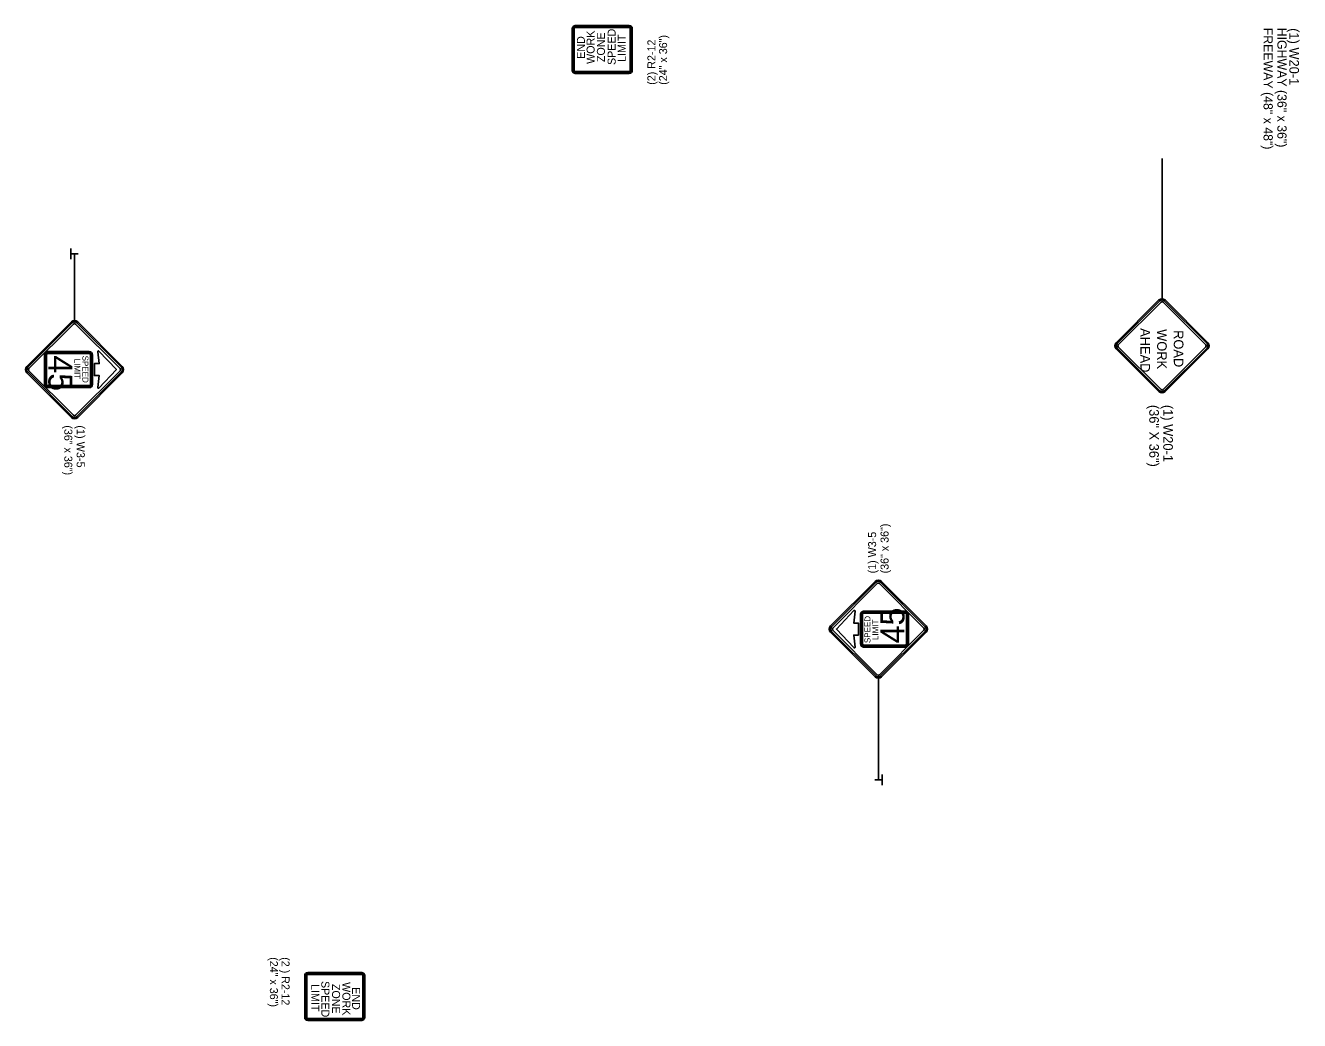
# Model space of a CAD drawing. Extents: x 1930579 to 1939784, y 596179 to 597522.
# Drawn here: x 1936300 to 1937255, y 596326 to 597073 of the extents above; entities that cross this region are included whole.
import ezdxf

# ---------------------------------------------------------------- set-up
doc = ezdxf.new("R2010")
doc.units = 0
for name, color, linetype in [('Default', 7, 'Continuous'), ('P_TC_Signs_Permanent', 7, 'Continuous'), ('P_TC_Signs_Temporary', 7, 'Continuous'), ('R_Annotation', 7, 'Continuous')]:
    doc.layers.add(name, color=color, linetype=linetype)

msp = doc.modelspace()

# ---------------------------------------------------------------- linework, layer by layer
at = {"layer": 'Default'}
for p, q in [((1936334.02, 596897.4), (1936334.02, 596905.4)), ((1936334.14, 596901.38), (1936339.61, 596901.38)), ((1936942.3, 596506.94), (1936936.84, 596506.94)), ((1936942.42, 596510.92), (1936942.42, 596502.91))]:
    msp.add_line(p, q, dxfattribs=at)
at = {"layer": 'P_TC_Signs_Permanent'}
for p, q in [((1936710.08, 597070.44), (1936710.08, 597038.94)), ((1936710.64, 597070.44), (1936710.64, 597038.94)), ((1936711.58, 597070.44), (1936711.58, 597038.94)), ((1936752.83, 597072.69), (1936712.33, 597072.69)), ((1936752.83, 597072.13), (1936712.33, 597072.13)), ((1936752.83, 597071.19), (1936712.33, 597071.19)), ((1936753.58, 597038.94), (1936753.58, 597070.44)), ((1936754.52, 597038.94), (1936754.52, 597070.44)), ((1936755.08, 597038.94), (1936755.08, 597070.44)), ((1936712.33, 597038.19), (1936752.83, 597038.19)), ((1936712.33, 597037.25), (1936752.83, 597037.25)), ((1936712.33, 597036.69), (1936752.83, 597036.69)), ((1936334.49, 596850.41), (1936301.08, 596816.99)), ((1936335.15, 596849.74), (1936301.74, 596816.33)), ((1936336.08, 596848.81), (1936302.67, 596815.4)), ((1936371.08, 596815.4), (1936337.67, 596848.81)), ((1936372.01, 596816.33), (1936338.6, 596849.74)), ((1936372.67, 596816.99), (1936339.26, 596850.41)), ((1936316.68, 596828.11), (1936347.88, 596828.11)), ((1936314.28, 596803.51), (1936314.28, 596825.71)), ((1936350.28, 596825.71), (1936350.28, 596803.51)), ((1936301.08, 596812.22), (1936334.49, 596778.81)), ((1936301.74, 596812.88), (1936335.15, 596779.47)), ((1936302.67, 596813.81), (1936336.08, 596780.4)), ((1936337.67, 596780.4), (1936371.08, 596813.81)), ((1936338.6, 596779.47), (1936372.01, 596812.88)), ((1936339.26, 596778.81), (1936372.67, 596812.22)), ((1936347.88, 596801.11), (1936316.68, 596801.11)), ((1936937.18, 596655.81), (1936903.77, 596622.4)), ((1936937.85, 596655.15), (1936904.43, 596621.74)), ((1936974.7, 596621.74), (1936941.29, 596655.15)), ((1936975.37, 596622.4), (1936941.96, 596655.81)), ((1936938.77, 596654.22), (1936905.36, 596620.81)), ((1936973.78, 596620.81), (1936940.36, 596654.22)), ((1936926.16, 596608.91), (1936926.16, 596631.11)), ((1936928.56, 596633.51), (1936959.76, 596633.51)), ((1936962.16, 596631.11), (1936962.16, 596608.91)), ((1936903.77, 596617.63), (1936937.18, 596584.22)), ((1936904.43, 596618.29), (1936937.85, 596584.88)), ((1936905.36, 596619.22), (1936938.77, 596585.81)), ((1936940.36, 596585.81), (1936973.78, 596619.22)), ((1936941.29, 596584.88), (1936974.7, 596618.29)), ((1936941.96, 596584.22), (1936975.37, 596617.63)), ((1936959.76, 596606.51), (1936928.56, 596606.51)), ((1936509.45, 596360.24), (1936509.45, 596328.74)), ((1936510.01, 596360.24), (1936510.01, 596328.74)), ((1936510.95, 596360.24), (1936510.95, 596328.74)), ((1936552.2, 596362.49), (1936511.7, 596362.49)), ((1936552.2, 596361.93), (1936511.7, 596361.93)), ((1936552.2, 596360.99), (1936511.7, 596360.99)), ((1936552.95, 596328.74), (1936552.95, 596360.24)), ((1936553.88, 596328.74), (1936553.88, 596360.24)), ((1936554.45, 596328.74), (1936554.45, 596360.24)), ((1936511.7, 596327.99), (1936552.2, 596327.99)), ((1936511.7, 596327.05), (1936552.2, 596327.05)), ((1936511.7, 596326.49), (1936552.2, 596326.49))]:
    msp.add_line(p, q, dxfattribs=at)
for points in [[(1936347.88, 596827.51), (1936316.68, 596827.51)], [(1936316.68, 596826.61), (1936347.88, 596826.61)], [(1936354.23, 596828.07), (1936355.35, 596819.11), (1936351.78, 596819.11), (1936351.78, 596810.11), (1936355.34, 596810.11), (1936354.23, 596801.22)], [(1936355.19, 596800.76), (1936368.28, 596814.64), (1936355.19, 596828.52)], [(1936314.88, 596825.71), (1936314.88, 596803.51)], [(1936315.78, 596803.51), (1936315.78, 596825.71)], [(1936348.78, 596825.71), (1936348.78, 596814.61), (1936348.78, 596803.51)], [(1936349.68, 596803.51), (1936349.68, 596814.61), (1936349.68, 596825.71)], [(1936347.88, 596802.61), (1936316.68, 596802.61)], [(1936316.68, 596801.71), (1936347.88, 596801.71)], [(1936921.25, 596633.86), (1936908.16, 596619.98), (1936921.25, 596606.1)], [(1936922.22, 596606.55), (1936921.1, 596615.51), (1936924.66, 596615.51), (1936924.66, 596624.51), (1936921.1, 596624.51), (1936922.22, 596633.4)], [(1936926.76, 596631.11), (1936926.76, 596620.01), (1936926.76, 596608.91)], [(1936927.66, 596608.91), (1936927.66, 596620.01), (1936927.66, 596631.11)], [(1936959.76, 596632.91), (1936928.56, 596632.91)], [(1936928.56, 596632.01), (1936959.76, 596632.01)], [(1936960.66, 596631.11), (1936960.66, 596608.91)], [(1936961.56, 596608.91), (1936961.56, 596631.11)], [(1936959.76, 596608.01), (1936928.56, 596608.01)], [(1936928.56, 596607.11), (1936959.76, 596607.11)]]:
    msp.add_lwpolyline(points, dxfattribs=at)
for centre, radius, start, end in [((1936712.33, 597070.44), 2.25, 90, 180), ((1936712.33, 597070.44), 1.69, 90, 180), ((1936712.33, 597070.44), 0.75, 90, 180), ((1936752.83, 597070.44), 2.25, 360, 90), ((1936752.83, 597070.44), 1.69, 360, 90), ((1936752.83, 597070.44), 0.75, 360, 90), ((1936712.33, 597038.94), 2.25, 180, 270), ((1936712.33, 597038.94), 1.69, 180, 270), ((1936712.33, 597038.94), 0.75, 180, 270), ((1936752.83, 597038.94), 2.25, 270, 360), ((1936752.83, 597038.94), 1.69, 270, 360), ((1936752.83, 597038.94), 0.75, 270, 360), ((1936336.87, 596848.02), 3.38, 45, 135), ((1936336.87, 596848.02), 2.44, 45, 135), ((1936336.87, 596848.02), 1.13, 45, 135), ((1936316.68, 596825.71), 2.4, 90, 180), ((1936316.68, 596825.71), 1.8, 90, 180), ((1936316.68, 596825.71), 0.9, 90, 180), ((1936347.88, 596825.71), 2.4, 360, 90), ((1936347.88, 596825.71), 1.8, 360, 90), ((1936347.88, 596825.71), 0.9, 360, 90), ((1936354.79, 596828.14), 0.563, 43.31166, 187.12501), ((1936303.46, 596814.61), 3.38, 135, 225), ((1936370.28, 596814.61), 3.38, 315, 45), ((1936303.46, 596814.61), 2.44, 135, 225), ((1936303.46, 596814.61), 1.13, 135, 225), ((1936370.28, 596814.61), 1.13, 315, 45), ((1936370.28, 596814.61), 2.44, 315, 45), ((1936316.68, 596803.51), 2.4, 180, 270), ((1936316.68, 596803.51), 1.8, 180, 270), ((1936316.68, 596803.51), 0.9, 180, 270), ((1936347.88, 596803.51), 2.4, 270, 360), ((1936347.88, 596803.51), 1.8, 270, 360), ((1936347.88, 596803.51), 0.9, 270, 360), ((1936354.79, 596801.15), 0.563, 172.87498, 316.68834), ((1936336.87, 596781.2), 3.38, 225, 315), ((1936336.87, 596781.2), 2.44, 225, 315), ((1936336.87, 596781.2), 1.13, 225, 315), ((1936939.57, 596653.42), 3.38, 45, 135), ((1936939.57, 596653.42), 2.44, 45, 135), ((1936939.57, 596653.42), 1.13, 45, 135), ((1936921.66, 596633.47), 0.563, 352.87498, 136.68834), ((1936928.56, 596631.11), 2.4, 90, 180), ((1936928.56, 596631.11), 1.8, 90, 180), ((1936928.56, 596631.11), 0.9, 90, 180), ((1936959.76, 596631.11), 2.4, 360, 90), ((1936959.76, 596631.11), 1.8, 360, 90), ((1936959.76, 596631.11), 0.9, 360, 90), ((1936906.16, 596620.01), 3.38, 135, 225), ((1936906.16, 596620.01), 2.44, 135, 225), ((1936906.16, 596620.01), 1.13, 135, 225), ((1936972.98, 596620.01), 1.13, 315, 45), ((1936972.98, 596620.01), 2.44, 315, 45), ((1936972.98, 596620.01), 3.38, 315, 45), ((1936921.66, 596606.48), 0.563, 223.31166, 7.12501), ((1936928.56, 596608.91), 2.4, 180, 270), ((1936928.56, 596608.91), 1.8, 180, 270), ((1936928.56, 596608.91), 0.9, 180, 270), ((1936959.76, 596608.91), 2.4, 270, 360), ((1936959.76, 596608.91), 1.8, 270, 360), ((1936959.76, 596608.91), 0.9, 270, 360), ((1936939.57, 596586.6), 3.38, 225, 315), ((1936939.57, 596586.6), 2.44, 225, 315), ((1936939.57, 596586.6), 1.13, 225, 315), ((1936511.7, 596360.24), 2.25, 90, 180), ((1936511.7, 596360.24), 1.69, 90, 180), ((1936511.7, 596360.24), 0.75, 90, 180), ((1936552.2, 596360.24), 2.25, 360, 90), ((1936552.2, 596360.24), 1.69, 360, 90), ((1936552.2, 596360.24), 0.75, 360, 90), ((1936511.7, 596328.74), 2.25, 180, 270), ((1936511.7, 596328.74), 1.69, 180, 270), ((1936511.7, 596328.74), 0.75, 180, 270), ((1936552.2, 596328.74), 2.25, 270, 360), ((1936552.2, 596328.74), 1.69, 270, 360), ((1936552.2, 596328.74), 0.75, 270, 360)]:
    msp.add_arc(centre, radius, start, end, dxfattribs=at)
at = {"layer": 'P_TC_Signs_Temporary'}
for p, q in [((1937117.92, 596834.77), (1937149.99, 596866.84)), ((1937118.55, 596834.13), (1937150.63, 596866.2)), ((1937119.44, 596833.24), (1937151.52, 596865.31)), ((1937153.04, 596865.31), (1937185.12, 596833.24)), ((1937153.94, 596866.2), (1937186.01, 596834.13)), ((1937154.57, 596866.84), (1937186.65, 596834.77)), ((1937149.99, 596798.11), (1937117.92, 596830.18)), ((1937150.63, 596798.75), (1937118.55, 596830.82)), ((1937151.52, 596799.64), (1937119.44, 596831.71)), ((1937185.12, 596831.71), (1937153.04, 596799.64)), ((1937186.01, 596830.82), (1937153.94, 596798.75)), ((1937186.65, 596830.18), (1937154.57, 596798.11))]:
    msp.add_line(p, q, dxfattribs=at)
for centre, radius, start, end in [((1937152.28, 596864.55), 3.24, 45, 135), ((1937152.28, 596864.55), 2.34, 45, 135), ((1937152.28, 596864.55), 1.08, 45, 135), ((1937120.21, 596832.47), 3.24, 135, 225), ((1937120.21, 596832.47), 2.34, 135, 225), ((1937120.21, 596832.47), 1.08, 135, 225), ((1937184.36, 596832.47), 1.08, 315, 45), ((1937184.36, 596832.47), 2.34, 315, 45), ((1937184.36, 596832.47), 3.24, 315, 45), ((1937152.28, 596800.4), 3.24, 225, 315), ((1937152.28, 596800.4), 2.34, 225, 315), ((1937152.28, 596800.4), 1.08, 225, 315)]:
    msp.add_arc(centre, radius, start, end, dxfattribs=at)
at = {"layer": 'R_Annotation'}
for p, q in [((1937152.28, 596972.99), (1937152.28, 596867.79)), ((1937152.28, 596972.99), (1937152.28, 596867.79)), ((1936336.87, 596901.38), (1936336.87, 596851.39)), ((1936939.57, 596506.94), (1936939.57, 596583.23))]:
    msp.add_line(p, q, dxfattribs=at)

# ---------------------------------------------------------------- texts
at = {"layer": 'P_TC_Signs_Permanent'}
for s, height, rotation, p in [('WORK', 6, 90, (1936726.82, 597043.89)), ('ZONE', 6, 90, (1936734.56, 597045.22)), ('SPEED', 6, 90, (1936742.58, 597043.05)), ('LIMIT', 6, 90, (1936750.21, 597045.4)), ('END', 6, 90, (1936719.53, 597047.7)), ('45', 18, 270, (1936317.28, 596825.29)), ('LIMIT', 4.5, 270, (1936336.78, 596822.8)), ('SPEED', 4.5, 270, (1936342.78, 596825.11)), ('SPEED', 4.5, 90, (1936933.66, 596609.51)), ('LIMIT', 4.5, 90, (1936939.66, 596611.82)), ('45', 18, 90, (1936959.16, 596609.33)), ('LIMIT', 6, 270, (1936514.32, 596353.78)), ('SPEED', 6, 270, (1936521.95, 596356.13)), ('ZONE', 6, 270, (1936529.96, 596353.96)), ('WORK', 6, 270, (1936537.7, 596355.29)), ('END', 6, 270, (1936545, 596351.48))]:
    msp.add_text(s, height=height, rotation=rotation, dxfattribs=at).set_placement(p)
at = {"layer": 'P_TC_Signs_Temporary'}
for s, p in [(' AHEAD ', (1937136.12, 596848.35)), ('WORK', (1937148.62, 596844.95)), (' ROAD ', (1937161.13, 596846.9))]:
    msp.add_text(s, height=7.2, rotation=270, dxfattribs=at).set_placement(p)
at = {"layer": 'R_Annotation'}
for s, height, rotation, p in [('FREEWAY (48" x 48")', 6.912, 270, (1937228.4, 597071.03)), ('HIGHWAY (36" x 36")', 6.912, 270, (1937238.77, 597071.03)), ('(1) W20-1', 7.2, 270, (1937247.79, 597070.67)), ('(2) R2-12', 6, 90, (1936772.42, 597028.2)), ('(24" x 36")', 5.9996, 90, (1936781.17, 597028.2)), ('(36" X 36")', 7.2, 270, (1937142.71, 596788.17)), ('(1) W20-1', 7.2, 270, (1937153.19, 596788.17)), ('(36" x 36")', 5.9996, 270, (1936329.19, 596772.82)), ('(1) W3-5', 6.1, 270, (1936338.45, 596772.82)), ('(1) W3-5', 6, 90, (1936937.89, 596661.8)), ('(36" x 36")', 6, 90, (1936947.25, 596661.8)), ('(24" x 36")', 5.9996, 270, (1936483.35, 596373.98)), ('(2 ) R2-12', 6, 270, (1936492.1, 596373.98))]:
    msp.add_text(s, height=height, rotation=rotation, dxfattribs=at).set_placement(p)

doc.saveas('drawing.dxf')
